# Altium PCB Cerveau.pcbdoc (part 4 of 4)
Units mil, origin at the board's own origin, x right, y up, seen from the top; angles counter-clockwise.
Board outline 3985.6 x 3546.5 mil, 2 copper layers (Top Layer, Bottom Layer), stack 62.2 mil thick; 170 components, 173 nets, 734 pads, 576 vias.
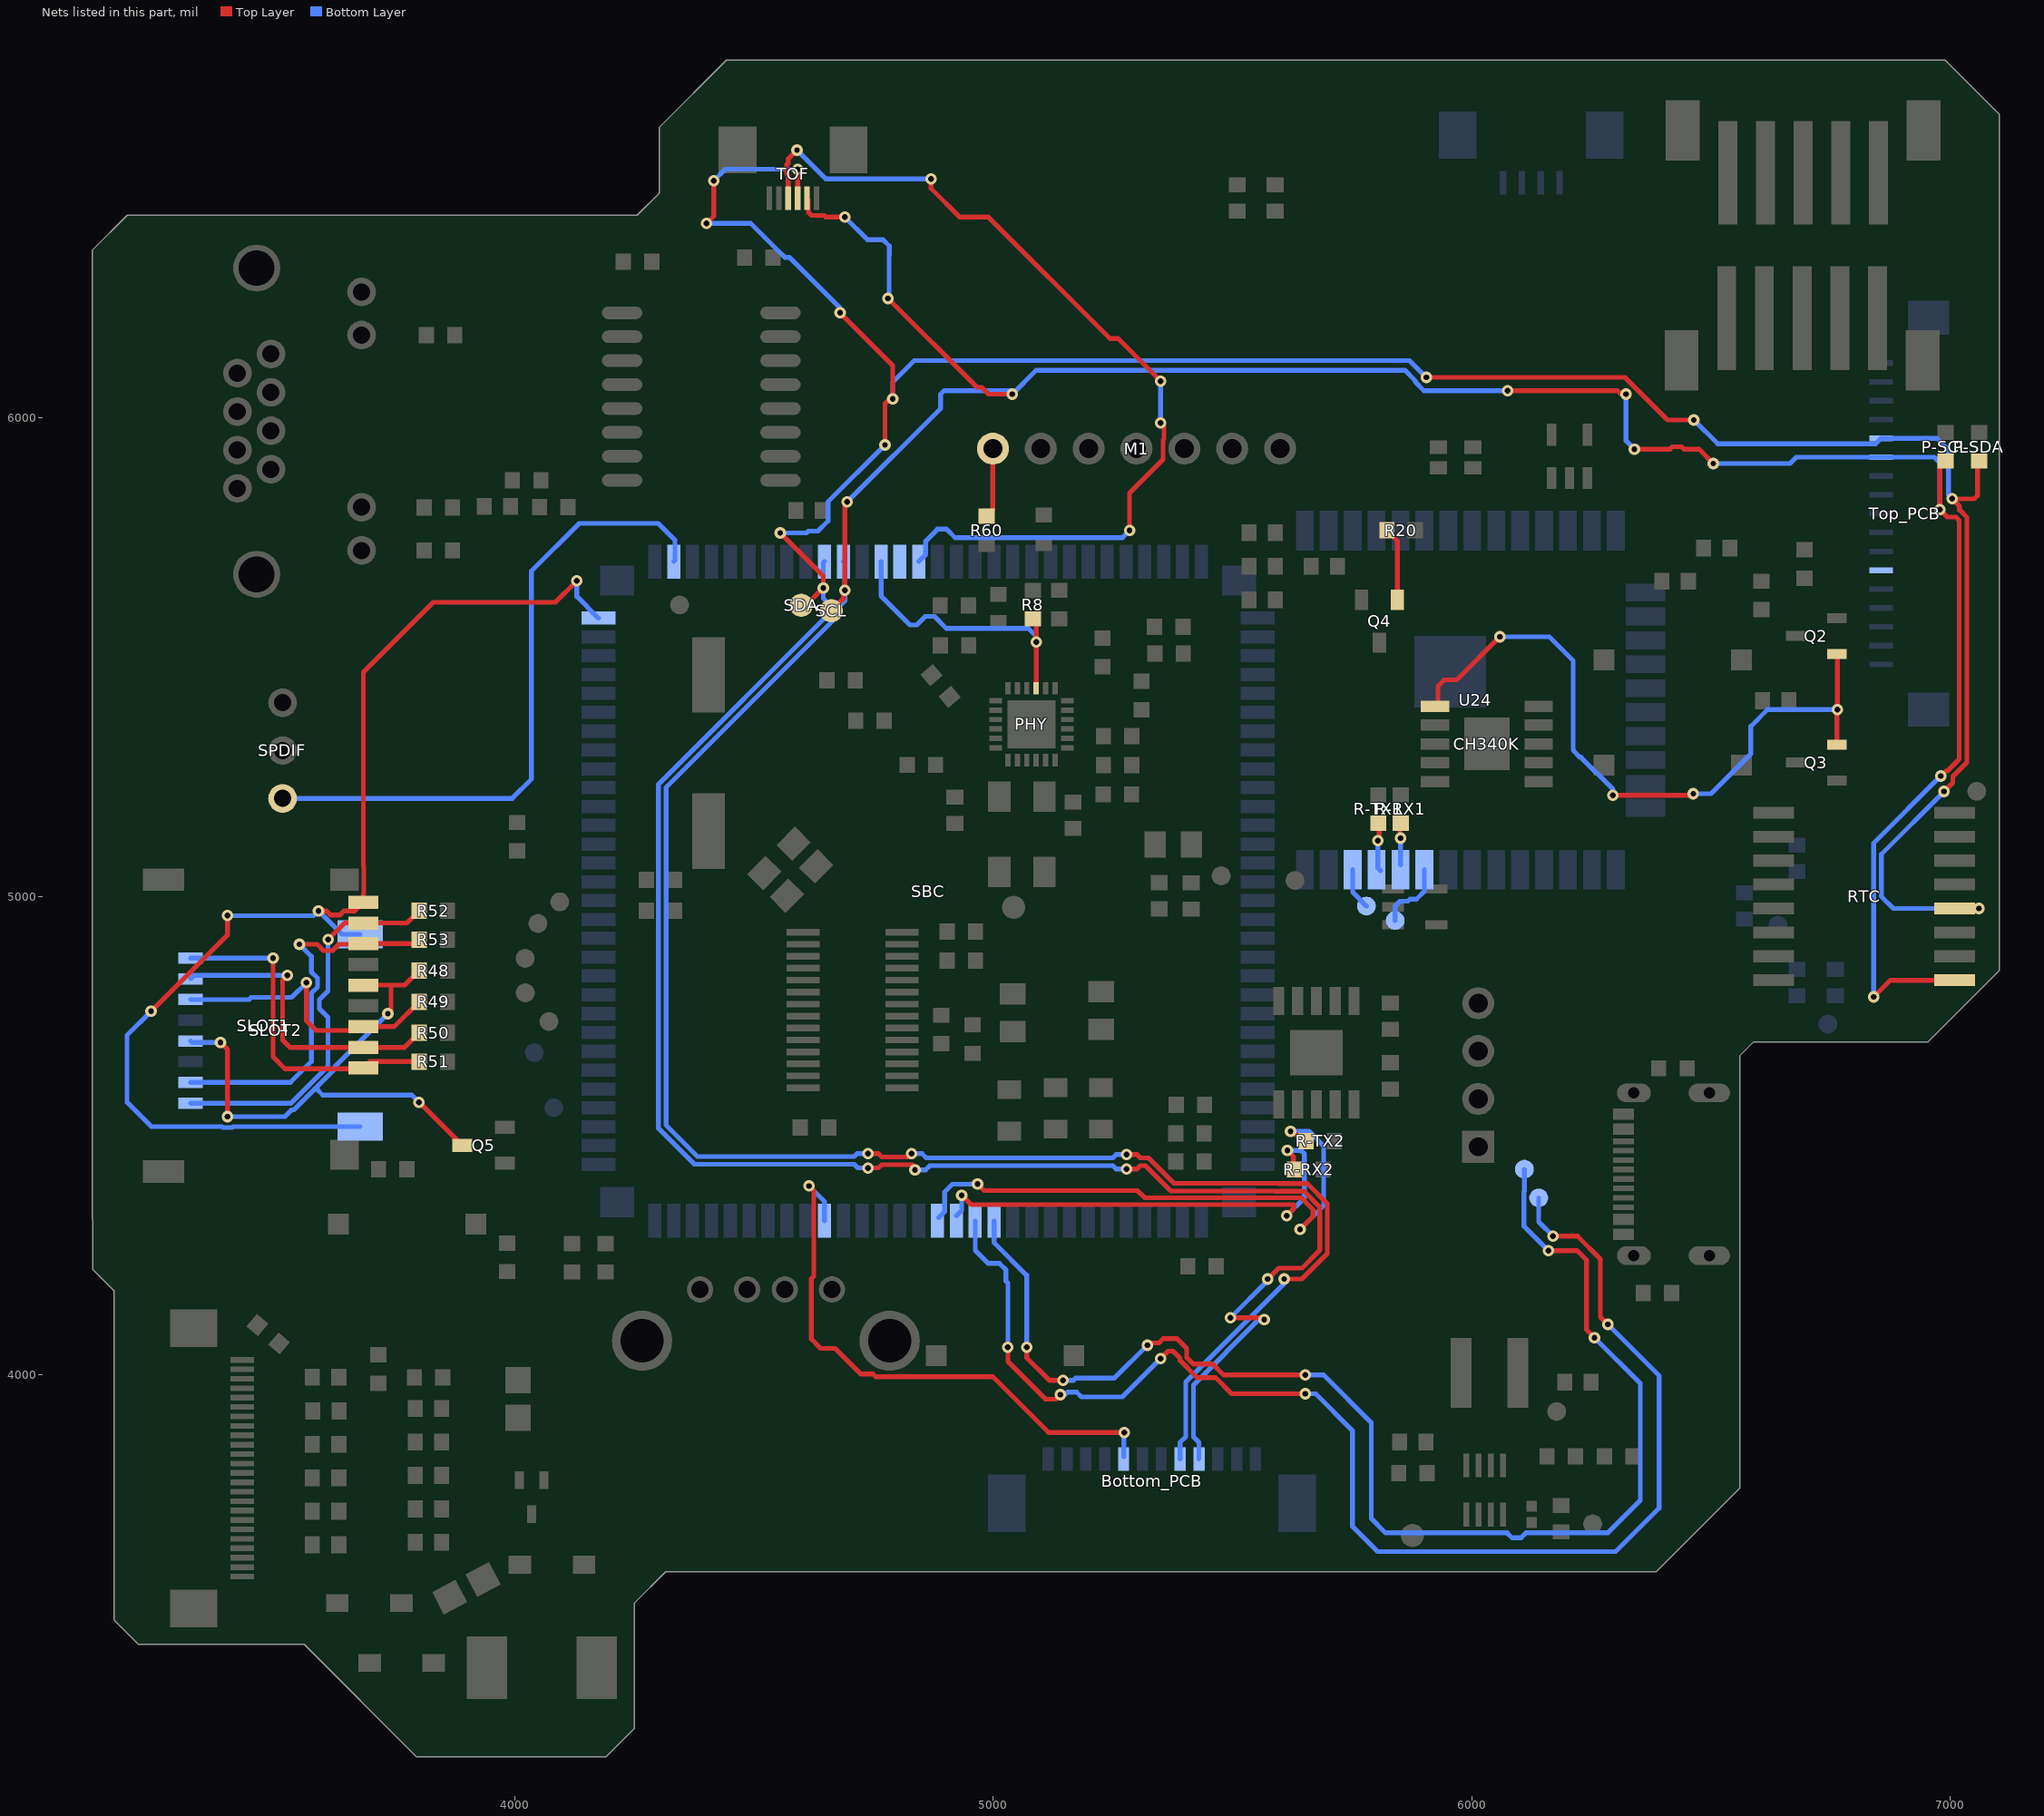
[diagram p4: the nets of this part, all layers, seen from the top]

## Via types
v1: diameter 24, hole 12, Top Layer to Bottom Layer, 576 vias

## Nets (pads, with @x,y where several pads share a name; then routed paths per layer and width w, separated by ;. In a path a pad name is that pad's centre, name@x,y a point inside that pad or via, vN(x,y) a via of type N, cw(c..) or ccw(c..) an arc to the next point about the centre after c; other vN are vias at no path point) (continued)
PHONE_R: Bottom_PCB.8 SBC.81 | length 1198.7
  Top Layer w10: v1(4615,4395) 4625.2,4384.8 4625.2,4206.2 4620,4201.1 4620,4075 4639.6,4055.4 4669.8,4055.4 4723.4,4001.8 4748.8,4001.8 4754.4,3996.2 4999.3,3996.2 5115.8,3879.6 v1(5273.8,3879.6)
  Bottom Layer w10: v1(4615,4395) 4647.4,4362.6 SBC.81@4647.4,4322 ; Bottom_PCB.8@5272.8,3828.9 5272.8,3878.6 v1(5273.8,3879.6)
PHY_RST: PHY.15 R8.1 SBC.13 | length 603.8
  Top Layer w10: R8.1@5082.9,5578.6 5089.8,5571.7 PHY.15@5089.8,5435.1
  Bottom Layer w10: SBC.13@4765.6,5700 4765.6,5628.2 4826.3,5567.5 4840.1,5567.5 4858,5585.4 4877,5585.4 4902.1,5560.3 5073.2,5560.3 5090,5543.4 v1(5090,5532.1)
RST: SBC.14
RST_CMPT: Q4.1 R20.1 | length 154.4
  Top Layer w10: R20.1@5822.6,5765.3 5844.6,5743.2 Q4.1@5844.6,5620
RTS: CH340K.6 Q2.1 Q3.2 | length 1474.4
  Top Layer w10: CH340K.6@5929.3,5393.8 5929.3,5439.5 5941.2,5451.3 ; 5942.1,5452.7 5968.7,5452.7 v1(6058.7,5542.8) ; v1(6295.2,5211.7) 6459.9,5211.7 v1(6463,5214.8) ; Q2.1@6763.3,5506.9 6764.2,5506.1 v1(6764.2,5390.7) 6763.4,5389.9 Q3.2@6763.4,5317.4
  Bottom Layer w10: v1(6058.7,5542.8) 6162.2,5542.8 6211.9,5493.1 6211.9,5307.4 6212.9,5306.4 6212.9,5304.4 6226.4,5290.9 6228.4,5290.9 6295.2,5224.1 v1(6295.2,5211.7) ; v1(6463,5214.8) 6499.9,5214.8 6583.2,5298.1 6583.2,5355.7 6618.1,5390.7 v1(6764.2,5390.7)
RX-1: R-RX1.2 U24.34 | length 84.7
  Top Layer w10: R-RX1.2@5849.7,5150.6 5849.7,5123.4 v1(5851.3,5121.8)
  Bottom Layer w10: U24.34@5851.3,5066.6 v1(5851.3,5121.8)
RX-2: R-RX2.2 SBC.74 | length 1007
  Top Layer w10: v1(4934.2,4375.6) 4953.8,4356 5627.4,4356 5628.6,4354.8 5628.6,4348.3 v1(5613.1,4332.7) ; v1(5614.8,4469.1) 5627.5,4456.4 R-RX2.2@5627.5,4430.1
  Bottom Layer w10: SBC.74@4922.9,4332.5 4934.2,4343.8 v1(4934.2,4375.6) ; v1(5613.1,4332.7) 5650.5,4370.2 5650.5,4462 5643.5,4469.1 v1(5614.8,4469.1)
SCL: Bottom_PCB.5 P-SCL.1 RTC.1 SBC.11 SCL.1 TOF.2 Top_PCB.12 | length 8491.5
  Top Layer w10: TOF.2@4611.1,6459.1 4613.9,6456.3 4613.9,6429.9 4620.3,6423.5 4646.7,6423.5 4650.2,6420 v1(4690,6420) ; SCL.1@4661.6,5597.3 4687.3,5623.1 v1@4687.3,5639.9 ; v1(4690,5640) 4690,5820 v1(4695,5825) ; v1(4738.2,4462.6) 4760.2,4462.6 4767.2,4455.6 4830.5,4455.6 4830.5,4461.3 v1(4829.2,4462.6) ; v1(4780,6250) 4966,6064 4975.8,6064 4989.8,6050 v1(5040,6050) ; v1(5278.9,4460.6) 5300.9,4460.6 5307.9,4453.6 5324.5,4453.6 5377.5,4400.6 5596.2,4400.6 5596.8,4400 5656.3,4400 5698.3,4358 5698.3,4253.5 5645.2,4200.4 v1(5608.2,4200.4) ; v1(6075,6057.1) 6305,6057.1 6312.1,6049.9 v1(6322.6,6049.9) ; v1(6340,5935) 6414.2,5935 6419.2,5940.1 6438.3,5940.1 6443.4,5935 6475,5935 v1(6505,5905) ; v1(6840,4790) 6875,4825 RTC.1@7009,4825 ; v1(6980.1,5251.7) 6990.8,5262.4 6994.1,5262.4 7018.7,5287 7018.7,5785.8 7011.6,5792.9 6993.9,5792.9 v1(6978.3,5808.5) 6978.3,5898.6 P-SCL.1@6990,5910.3
  Bottom Layer w10: SBC.11@4686.8,5700 4690,5696.8 v1(4690,5640) 4690,5618 4675.5,5603.5 4675.5,5586.9 4316.6,5227.9 4316.6,4522 4382,4456.5 4709.2,4456.5 4715.2,4462.6 v1(4738.2,4462.6) ; v1(4690,6420) 4737,6373 4769.5,6373 4783,6359.5 4783,6340.5 4782.5,6340 4782.5,6252.5 v1(4780,6250) ; v1(4695,5825) 4890,6020 4890,6050 4897.1,6057.1 v1@5040,6057.1 ; v1(4829.2,4462.6) 4851.2,4462.6 4860.2,4453.6 5249.9,4453.6 5256.9,4460.6 v1(5278.9,4460.6) ; v1(5040,6050) 5090,6100 5860,6100 5882,6078 5882,6075.5 5900.4,6057.1 v1(6075,6057.1) ; Bottom_PCB.5@5390.6,3824.3 5390.6,3858.9 5402.3,3870.6 5402.3,3985.4 5607,4190.2 v1@5607,4199.8 ; v1(6322.6,6049.9) 6322.6,5952.4 v1(6340,5935) ; v1(6505,5905) 6665,5905 6678.1,5918.1 Top_PCB.12@6855.3,5918.1 6966.3,5918.1 6978.3,5906.2 v1(6978.3,5808.5) ; v1(6840,4790) 6840,5111.6 v1(6980.1,5251.7)
SCL_ESP: pad.1@5780,4980 pad.1@6110,4430 SBC.72 U24.36 | length 2901.6
  Top Layer w10: v1(5070,4058) 5070,4036 5117.1,3988.9 v1(5145.7,3988.9) ; v1(5322.2,4062.2) 5327,4067 5346.5,4067 5355.5,4076 5383.4,4076 5404.1,4055.4 5404.1,4036.3 5417.6,4022.9 5458.3,4022.9 5481.1,4000 v1(5652,4000) ; v1(6160,4260) 6220,4260 6240,4240 6240,4094.3 v1(6256.6,4077.7)
  Bottom Layer w10: SBC.72@5001.8,4322 5001.8,4276.6 5070,4208.4 v1(5070,4058) ; v1(5145.7,3988.9) 5167.7,3988.9 5172.4,3993.6 5253.6,3993.6 v1(5322.2,4062.2) ; v1(5652,4000) 5690.3,4000 5790,3900.3 5790,3700 5820,3670 6073.9,3670 6084.1,3659.7 6103.2,3659.7 6113.4,3670 6284.3,3670 6352.2,3737.8 6352.2,3982.2 v1(6256.6,4077.7) ; U24.36@5751.1,5056 5751.1,5008.9 pad.1@5780,4980 ; pad.1@6110,4430 6110,4383.4 6109.3,4382.7 6109.3,4310.7 v1(6160,4260)
SD_CD: SBC.120 SLOT1.CD SLOT2.9 | length 2500.8
  Top Layer w10: v1(3240,4760) 3400,4920 v1(3400,4960) ; v1(3590,4970) 3606.6,4970 3615.5,4961.1 3634.5,4961.1 3643.4,4970 3665.8,4970 SLOT1.CD@3683.7,4987.9 3683.7,5005.8 3684.8,5006.9 3684.8,5063.3 3683.7,5064.4 3683.7,5468.7 3830,5615 4085,5615 v1(4130,5660)
  Bottom Layer w10: v1(3240,4760) 3190,4710 3190,4570 3240.8,4519.2 3388.3,4519.2 3390.5,4517 3409.5,4517 3411.7,4519.2 SLOT2.9@3677,4519.2 ; v1(3400,4960) 3580,4960 v1(3590,4970) 3639.2,4920.8 SLOT2.9@3677,4920.8 ; v1(4130,5660) 4130,5626.9 SBC.120@4175,5581.9
SD_CLK: Q5.3 R48.2 SLOT1.5 SLOT2.5 | length 1198.6
  Top Layer w10: v1(3385,4695) 3400,4680 v1(3400,4540) ; SLOT1.5@3683.7,4814.6 3741.4,4814.6 ; v1(3735,4755) 3741.4,4761.4 3741.4,4814.6 ; v1(3800,4570) 3800.3,4570 Q5.3@3890.3,4480 ; R48.2@3800.3,4845 3770,4814.6 3741.4,4814.6
  Bottom Layer w10: SLOT2.5@3322.7,4698 3325.7,4695 v1(3385,4695) ; v1(3400,4540) 3520,4540 3534.1,4554.1 3538.9,4554.1 3584.3,4599.5 ; v1(3735,4755) 3624,4644 3624,4639.2 3584.3,4599.5 ; v1(3800,4570) 3785,4585 3598.8,4585 3584.3,4599.5
SD_CMD: R49.2 SLOT1.3 SLOT2.3 | length 605.4
  Top Layer w10: v1(3565,4820) 3565,4740 3585,4720 3675.6,4720 SLOT1.3@3683.7,4728 3748.4,4728 R49.2@3800.3,4780
  Bottom Layer w10: SLOT2.3@3322.7,4784.6 3444.8,4784.6 3449.2,4789 3534,4789 v1(3565,4820)
SD_DAT0: R53.2 SLOT1.7 SLOT2.7 | length 801.7
  Top Layer w10: v1(3550,4900) 3587.5,4900 3600.5,4887 3619.5,4887 3632.5,4900 3682.4,4900 SLOT1.7@3683.7,4901.3 3791.6,4901.3 R53.2@3800.3,4910
  Bottom Layer w10: SLOT2.7@3322.7,4611.4 3531.4,4611.4 3575,4655 3575,4797.5 3588,4810.5 3588,4829.5 3575,4842.5 3575,4875 v1(3550,4900)
SD_DAT1: R52.2 SLOT1.8 SLOT2.8 | length 814.2
  Top Layer w10: v1(3610,4910) 3644.6,4944.6 SLOT1.8@3683.7,4944.6 3774.9,4944.6 R52.2@3800.3,4970
  Bottom Layer w10: SLOT2.8@3322.7,4568.1 3533.1,4568.1 3610,4645 3610,4747.5 3592,4765.5 3592,4784.5 3610,4802.5 v1(3610,4910)
SD_DAT2: R51.2 SLOT1.1 SLOT2.1 | length 700.4
  Top Layer w10: v1(3495,4871.2) 3495,4665 3520,4640 3682.3,4640 SLOT1.1@3683.7,4641.4 3697.3,4655 R51.2@3800.3,4655
  Bottom Layer w10: SLOT2.1@3322.7,4871.2 v1(3495,4871.2)
SD_DAT3: R50.2 SLOT1.2 SLOT2.2 | length 648.6
  Top Layer w10: v1(3525,4835) 3515,4825 3515,4700 3530.3,4684.7 SLOT1.2@3683.7,4684.7 3770.1,4684.7 R50.2@3800.3,4715
  Bottom Layer w10: SLOT2.2@3322.7,4827.9 3329.8,4835 v1(3525,4835)
SDA: Bottom_PCB.4 P-SDA.1 RTC.4 SBC.10 SDA.1 TOF.3 Top_PCB.13 | length 8917.7
  Top Layer w10: v1(4401.1,6407) 4416.1,6422 v1(4416.1,6496.1) ; v1(4555,5760) 4645,5670 v1(4645,5645) 4606.5,5606.5 SDA.1@4600.4,5606.5 ; TOF.3@4591.4,6459.1 v1(4591.4,6520) ; v1(4680,6220) 4790,6110 v1(4790,6040) 4783.8,6040 4773.8,6030 v1(4773.8,5943.8) ; v1(4738.2,4432.6) 4760.2,4432.6 4767.2,4439.6 4830.5,4439.6 4836.5,4433.5 v1(4836.5,4428.6) ; v1(5278.9,4430.6) 5300.9,4430.6 5307.9,4437.6 5317.9,4437.6 5370.9,4384.6 5589.6,4384.6 5590.2,4384 5649.7,4384 5682.3,4351.4 5682.3,4260.2 5645.6,4223.4 5596.7,4223.4 v1(5573.7,4200.4) ; v1(5495.8,4119.5) 5562.7,4119.5 v1(5566.4,4115.8) ; v1(5905,6085) 6320,6085 6409,5996 v1(6464,5996) ; v1(6987.2,5219.5) 7005.4,5237.7 7005.4,5251.1 7034.7,5280.3 7034.7,5792.5 7019.3,5807.9 7019.3,5815.7 v1(7003.7,5831.2) 7050,5831.2 7057.1,5838.3 7057.1,5907.4 P-SDA.1@7060,5910.3 ; RTC.4@7009,4975 v1(7060,4975)
  Bottom Layer w10: v1(4401.1,6407) 4493.2,6407 4550.2,6350 4564.2,6336 4574,6336 4680,6230 v1(4680,6220) ; v1(4416.1,6496.1) 4440,6520 v1(4591.4,6520) ; v1(4555,5760) 4609.9,5760 4613.8,5763.9 4633.9,5763.9 4655,5785 4655,5825 v1(4773.8,5943.8) ; SBC.10@4647.4,5700 4645,5697.6 v1(4645,5645) 4645,5623 4659.5,5608.5 4659.5,5593.5 4300.6,5234.6 4300.6,4515.3 4375.4,4440.5 4709.2,4440.5 4717.2,4432.6 v1(4738.2,4432.6) ; v1(4790,6040) 4790,6075 4835,6120 5870,6120 v1(5905,6085) ; v1(4836.5,4428.6) 4858.5,4428.6 4867.5,4437.6 5249.9,4437.6 5256.9,4430.6 v1(5278.9,4430.6) ; Bottom_PCB.4@5430,3824.3 5430,3858.9 5418.3,3870.6 5418.3,3978.8 5555.2,4115.8 v1(5566.4,4115.8) ; v1(5495.8,4119.5) 5573.7,4197.4 v1(5573.7,4200.4) ; v1(6464,5996) 6514,5946.1 6843.9,5946.1 Top_PCB.13@6855.3,5957.5 6972.1,5957.5 6996.3,5933.3 6996.3,5838.7 v1(7003.7,5831.2) ; v1(6987.2,5219.5) 6856,5088.2 6856,5000 6881,4975 v1(7060,4975)
SDA_ESP: pad.1@5840,4950 pad.1@6140,4370 SBC.73 U24.33 | length 3042
  Top Layer w10: v1(5030.6,4058) 5030.6,4028.1 5109.2,3949.5 5131.1,3949.5 v1(5140.5,3958.9) ; v1(5350,4034.3) 5365.6,4049.9 5375.6,4049.9 5390.1,4035.4 5390.1,4030.5 5426.3,3994.3 5464.7,3994.3 5498.4,3960.6 v1(5652,3960.6) ; v1(6170,4290) 6221,4290 6268.9,4242.1 6268.9,4121.1 v1(6284.4,4105.6)
  Bottom Layer w10: SBC.73@4962.4,4322 4962.4,4260.3 4989.7,4233 5013.2,4233 5026.7,4219.5 5026.7,4196 5030.6,4192.1 v1(5030.6,4058) ; v1(5140.5,3958.9) 5150.4,3958.9 5155.5,3964 5174.5,3964 5184.3,3954.2 5269.9,3954.2 v1(5350,4034.3) ; v1(5652,3960.6) 5674,3960.6 5750.6,3884 5750.6,3683.7 5803.7,3630.6 6300.6,3630.6 6391.5,3721.5 6391.5,3998.5 v1(6284.4,4105.6) ; pad.1@5840,4950 5840,4980 5850,4990 5866.2,4990 5870.7,4994.5 5884.5,4994.5 5901.1,5011.1 U24.33@5901.1,5056 ; pad.1@6140,4370 6140,4320 v1(6170,4290)
SPDIF: SBC.2 SPDIF.1 | length 1373.5
  Bottom Layer w10: SPDIF.1@3515,5205 3995,5205 4035,5245 4035,5680 4135,5780 4300,5780 4335,5745 4335,5702.5 SBC.2@4332.5,5700
TX-1: R-TX1.2 U24.35 | length 101.7
  Top Layer w10: v1(5804.1,5117) 5806.5,5119.4 R-TX1.2@5806.5,5152.2
  Bottom Layer w10: v1(5804.1,5117) 5804.1,5059.4 U24.35@5809.7,5053.8
TX-2: R-TX2.2 SBC.75 | length 1224.4
  Top Layer w10: v1(4967.2,4399.2) 4981,4385.4 5301.3,4385.4 5316.8,4370 5643.9,4370 5668.3,4345.6 5668.3,4331.2 v1(5641.4,4304.4) ; v1(5621.5,4509.2) 5626.4,4509.2 R-TX2.2@5650.1,4485.5
  Bottom Layer w10: SBC.75@4886.4,4329.2 4898.3,4341.1 4898.3,4382.1 4914.7,4398.6 4955.7,4398.6 4956.4,4399.2 v1(4967.2,4399.2) ; v1(5621.5,4509.2) 5660.1,4509.2 5690.7,4478.6 5690.7,4353.6 v1(5641.4,4304.4)
WS: Top_PCB.6
WS/LRCLK: M1.1 R60.2 | length 144.3
  Top Layer w10: R60.2@4986.6,5795 4998.8,5807.2 M1.1@4998.8,5934.2
XSHUT: SBC.15 TOF.4 | length 1926.9
  Top Layer w10: TOF.4@4571.7,6459.1 4571.7,6507.2 4568.4,6510.5 4568.4,6529.5 4571.7,6532.8 4571.7,6541.7 v1(4590,6560) ; v1(4870,6500) 4870,6480 4930,6420 4990,6420 5244,6166 5261,6166 v1(5350,6077) ; v1(5285,5765) 5285,5843.5 5355,5913.5 5355,5954.4 5357.1,5956.4 5357.1,5982.9 v1(5350,5990)
  Bottom Layer w10: v1(4590,6560) 4650,6500 v1(4870,6500) ; SBC.15@4844.3,5700 4858.9,5714.6 4858.9,5743 4883.6,5767.8 4902.7,5767.8 4920.4,5750 5270,5750 v1(5285,5765) ; v1(5350,5990) v1(5350,6077)
pads on no net: Buck_1.1 CH340K-2.4 CH340K-2.5 CH340K-2.6 CH340K.5 E-INK.1 E-INK.6 E-INK.7 FILT.12 FILT.13 LED16.1 M1.4 PHY.2 RJ45.4 RJ45.5 RJ45.7 RJ45.8 RTC.3 RTC.6 RTC.7 RTC.9 RTC.10 RTC.11 RTC.12 RTC.13 SBC.17 SBC.18 SBC.19 SBC.20 SBC.21 SBC.22 SBC.23 SBC.24 SBC.25 SBC.26 SBC.27 SBC.28 SBC.39 SBC.46 SBC.47 SBC.48 SBC.49 SBC.50 SBC.51 SBC.52 SBC.53 SBC.54 SBC.55 SBC.56 SBC.57 SBC.62 SBC.63 SBC.64 SBC.67 SBC.69 SBC.71 SBC.76 SBC.77 SBC.78 SBC.79 SBC.83 SBC.84 SBC.85 SBC.86 SBC.87 SBC.88 SBC.89 SBC.90 SBC.91 SBC.92 SBC.95 SBC.104 U24.4 U24.5 U24.6 U24.8 U24.9 U24.12 U24.13 U24.14 U24.16 U24.17 U24.18 U24.19 U24.20 U24.21 U24.22 U24.23 U24.24 U24.26 U24.27 U24.29 U24.32 USB-C2.A8 USB-C2.B8 USB_SWITCH.4 USB_SWITCH.5 USB_SWITCH.12 USB_SWITCH.13 USB_SWITCH.21 USB_SWITCH.27 USB_SWITCH.28 X3.2 X3.4

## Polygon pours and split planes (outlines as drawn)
GND on Top Layer (solid, remove dead copper, pour order 2): 3000,6850 3000,3000 7220,3000 7220,6850
5V on Top Layer (solid, remove dead copper, pour order 0): 6723,5806.7 6724.9,6630 6723.2,6630.3 6723.3,6653.5 6896.7,6653.9 6895.4,6499.1 6935.2,6454.5 6935.2,6211.7 6931.8,6208.3 6909.9,6208.3 6896.6,6195.1 6896.6,5996.9 6956.9,5936.6 6964.7,4847.6 6830,4710 6160.7,4710 6160.7,4854.7 6218.2,4910.8 6778.2,4910.9 6820.3,4972.7 6820.3,5719.6
GND on Bottom Layer (solid, remove dead copper, pour order 10): 3010,6850 3010,3110 7200,3110 7200,6850
5V on Bottom Layer (solid, remove dead copper, pour order 8): 6171.6,4860.3 6217.3,4906 6500.8,4906 6502.7,4904.1 6502.7,4806.1 6479.9,4783.2 6288.7,4783.2 6255.4,4749.9 6255.4,4311.4 6174.5,4311 6174.5,4602.4 6171.6,4605.3

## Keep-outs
Board Outline Layer:
  region: 4411.3,6558.4 4410.9,6552.9 4409.7,6547.5 4407.8,6542.4 4405.3,6537.5 4402,6533.1 4398.2,6529.1 4393.9,6525.8 4389.1,6523 4384,6520.9 4378.7,6519.6 4373.3,6519 4367.8,6519.2 4362.4,6520.2 4357.1,6521.9 4352.2,6524.3 4347.6,6527.4 4343.6,6531 4340,6535.3 4337.1,6539.9 4334.9,6544.9 4333.4,6550.2 4332.6,6555.6 4332.6,6561.1 4333.4,6566.6 4334.9,6571.9 4337.1,6576.9 4340,6581.5 4343.6,6585.7 4347.6,6589.4 4352.2,6592.5 4357.1,6594.9 4362.4,6596.6 4367.8,6597.5 4373.3,6597.7 4378.7,6597.2 4384,6595.8 4389.1,6593.8 4393.9,6591 4398.2,6587.6 4402,6583.7 4405.3,6579.3 4407.8,6574.4 4409.7,6569.2 4410.9,6563.9
  region: 4411.3,6558.4 4410.9,6552.9 4409.7,6547.5 4407.8,6542.4 4405.3,6537.5 4402,6533.1 4398.2,6529.1 4393.9,6525.8 4389.1,6523 4384,6520.9 4378.7,6519.6 4373.3,6519 4367.8,6519.2 4362.4,6520.2 4357.1,6521.9 4352.2,6524.3 4347.6,6527.4 4343.6,6531 4340,6535.3 4337.1,6539.9 4334.9,6544.9 4333.4,6550.2 4332.6,6555.6 4332.6,6561.1 4333.4,6566.6 4334.9,6571.9 4337.1,6576.9 4340,6581.5 4343.6,6585.7 4347.6,6589.4 4352.2,6592.5 4357.1,6594.9 4362.4,6596.6 4367.8,6597.5 4373.3,6597.7 4378.7,6597.2 4384,6595.8 4389.1,6593.8 4393.9,6591 4398.2,6587.6 4402,6583.7 4405.3,6579.3 4407.8,6574.4 4409.7,6569.2 4410.9,6563.9
  region: 3235.1,4311.8 3234.7,4306.3 3233.6,4301 3231.7,4295.8 3229.1,4290.9 3225.9,4286.5 3222.1,4282.6 3217.8,4279.2 3213,4276.4 3207.9,4274.4 3202.6,4273 3197.1,4272.5 3191.6,4272.7 3186.2,4273.6 3181,4275.3 3176.1,4277.7 3171.5,4280.8 3167.4,4284.5 3163.9,4288.7 3161,4293.3 3158.8,4298.3 3157.2,4303.6 3156.5,4309.1 3156.5,4314.6 3157.2,4320 3158.8,4325.3 3161,4330.3 3163.9,4335 3167.4,4339.2 3171.5,4342.8 3176.1,4345.9 3181,4348.3 3186.2,4350 3191.6,4351 3197.1,4351.2 3202.6,4350.6 3207.9,4349.3 3213,4347.2 3217.8,4344.4 3222.1,4341.1 3225.9,4337.1 3229.1,4332.7 3231.7,4327.8 3233.6,4322.7 3234.7,4317.3
  region: 3235.1,4311.8 3234.7,4306.3 3233.6,4301 3231.7,4295.8 3229.1,4290.9 3225.9,4286.5 3222.1,4282.6 3217.8,4279.2 3213,4276.4 3207.9,4274.4 3202.6,4273 3197.1,4272.5 3191.6,4272.7 3186.2,4273.6 3181,4275.3 3176.1,4277.7 3171.5,4280.8 3167.4,4284.5 3163.9,4288.7 3161,4293.3 3158.8,4298.3 3157.2,4303.6 3156.5,4309.1 3156.5,4314.6 3157.2,4320 3158.8,4325.3 3161,4330.3 3163.9,4335 3167.4,4339.2 3171.5,4342.8 3176.1,4345.9 3181,4348.3 3186.2,4350 3191.6,4351 3197.1,4351.2 3202.6,4350.6 3207.9,4349.3 3213,4347.2 3217.8,4344.4 3222.1,4341.1 3225.9,4337.1 3229.1,4332.7 3231.7,4327.8 3233.6,4322.7 3234.7,4317.3
  region: 4949,3809.6 4948.6,3804.1 4947.4,3798.7 4945.6,3793.6 4943,3788.7 4939.7,3784.3 4935.9,3780.3 4931.6,3776.9 4926.8,3774.2 4921.8,3772.1 4916.4,3770.8 4911,3770.2 4905.5,3770.4 4900.1,3771.4 4894.8,3773.1 4889.9,3775.5 4885.3,3778.6 4881.3,3782.2 4877.7,3786.4 4874.8,3791.1 4872.6,3796.1 4871.1,3801.4 4870.3,3806.8 4870.3,3812.3 4871.1,3817.8 4872.6,3823 4874.8,3828.1 4877.7,3832.7 4881.3,3836.9 4885.3,3840.6 4889.9,3843.7 4894.8,3846.1 4900.1,3847.8 4905.5,3848.7 4911,3848.9 4916.4,3848.3 4921.8,3847 4926.8,3845 4931.6,3842.2 4935.9,3838.8 4939.7,3834.9 4943,3830.4 4945.6,3825.6 4947.4,3820.4 4948.6,3815.1
  region: 4949,3809.6 4948.6,3804.1 4947.4,3798.7 4945.6,3793.6 4943,3788.7 4939.7,3784.3 4935.9,3780.3 4931.6,3776.9 4926.8,3774.2 4921.8,3772.1 4916.4,3770.8 4911,3770.2 4905.5,3770.4 4900.1,3771.4 4894.8,3773.1 4889.9,3775.5 4885.3,3778.6 4881.3,3782.2 4877.7,3786.4 4874.8,3791.1 4872.6,3796.1 4871.1,3801.4 4870.3,3806.8 4870.3,3812.3 4871.1,3817.8 4872.6,3823 4874.8,3828.1 4877.7,3832.7 4881.3,3836.9 4885.3,3840.6 4889.9,3843.7 4894.8,3846.1 4900.1,3847.8 4905.5,3848.7 4911,3848.9 4916.4,3848.3 4921.8,3847 4926.8,3845 4931.6,3842.2 4935.9,3838.8 4939.7,3834.9 4943,3830.4 4945.6,3825.6 4947.4,3820.4 4948.6,3815.1
  region: 6486.3,4030.8 6485.9,4025.3 6484.8,4019.9 6482.9,4014.8 6480.3,4009.9 6477.1,4005.5 6473.3,4001.5 6468.9,3998.1 6464.2,3995.4 6459.1,3993.3 6453.8,3992 6448.3,3991.4 6442.8,3991.6 6437.4,3992.6 6432.2,3994.3 6427.2,3996.7 6422.7,3999.8 6418.6,4003.4 6415.1,4007.6 6412.2,4012.3 6409.9,4017.3 6408.4,4022.6 6407.6,4028 6407.6,4033.5 6408.4,4039 6409.9,4044.3 6412.2,4049.3 6415.1,4053.9 6418.6,4058.1 6422.7,4061.8 6427.2,4064.9 6432.2,4067.3 6437.4,4069 6442.8,4069.9 6448.3,4070.1 6453.8,4069.6 6459.1,4068.2 6464.2,4066.2 6468.9,4063.4 6473.3,4060 6477.1,4056.1 6480.3,4051.6 6482.9,4046.8 6484.8,4041.6 6485.9,4036.3
  region: 6486.3,4030.8 6485.9,4025.3 6484.8,4019.9 6482.9,4014.8 6480.3,4009.9 6477.1,4005.5 6473.3,4001.5 6468.9,3998.1 6464.2,3995.4 6459.1,3993.3 6453.8,3992 6448.3,3991.4 6442.8,3991.6 6437.4,3992.6 6432.2,3994.3 6427.2,3996.7 6422.7,3999.8 6418.6,4003.4 6415.1,4007.6 6412.2,4012.3 6409.9,4017.3 6408.4,4022.6 6407.6,4028 6407.6,4033.5 6408.4,4039 6409.9,4044.3 6412.2,4049.3 6415.1,4053.9 6418.6,4058.1 6422.7,4061.8 6427.2,4064.9 6432.2,4067.3 6437.4,4069 6442.8,4069.9 6448.3,4070.1 6453.8,4069.6 6459.1,4068.2 6464.2,4066.2 6468.9,4063.4 6473.3,4060 6477.1,4056.1 6480.3,4051.6 6482.9,4046.8 6484.8,4041.6 6485.9,4036.3
  region: 7054.9,6394.5 7054.5,6389 7053.3,6383.6 7051.5,6378.5 7048.9,6373.6 7045.7,6369.2 7041.8,6365.2 7037.5,6361.9 7032.8,6359.1 7027.7,6357.1 7022.3,6355.7 7016.9,6355.2 7011.4,6355.3 7006,6356.3 7000.7,6358 6995.8,6360.4 6991.3,6363.5 6987.2,6367.1 6983.6,6371.4 6980.7,6376 6978.5,6381 6977,6386.3 6976.2,6391.8 6976.2,6397.2 6977,6402.7 6978.5,6408 6980.7,6413 6983.6,6417.6 6987.2,6421.8 6991.3,6425.5 6995.8,6428.6 7000.7,6431 7006,6432.7 7011.4,6433.7 7016.9,6433.8 7022.3,6433.3 7027.7,6431.9 7032.8,6429.9 7037.5,6427.1 7041.8,6423.8 7045.7,6419.8 7048.9,6415.4 7051.5,6410.5 7053.3,6405.3 7054.5,6400
  region: 7054.9,6394.5 7054.5,6389 7053.3,6383.6 7051.5,6378.5 7048.9,6373.6 7045.7,6369.2 7041.8,6365.2 7037.5,6361.9 7032.8,6359.1 7027.7,6357.1 7022.3,6355.7 7016.9,6355.2 7011.4,6355.3 7006,6356.3 7000.7,6358 6995.8,6360.4 6991.3,6363.5 6987.2,6367.1 6983.6,6371.4 6980.7,6376 6978.5,6381 6977,6386.3 6976.2,6391.8 6976.2,6397.2 6977,6402.7 6978.5,6408 6980.7,6413 6983.6,6417.6 6987.2,6421.8 6991.3,6425.5 6995.8,6428.6 7000.7,6431 7006,6432.7 7011.4,6433.7 7016.9,6433.8 7022.3,6433.3 7027.7,6431.9 7032.8,6429.9 7037.5,6427.1 7041.8,6423.8 7045.7,6419.8 7048.9,6415.4 7051.5,6410.5 7053.3,6405.3 7054.5,6400
  region: 5872.9,6662.5 5872.6,6657 5871.4,6651.6 5869.5,6646.5 5867,6641.6 5863.7,6637.2 5859.9,6633.2 5855.6,6629.9 5850.8,6627.1 5845.7,6625 5840.4,6623.7 5834.9,6623.1 5829.5,6623.3 5824,6624.3 5818.8,6626 5813.9,6628.4 5809.3,6631.5 5805.2,6635.1 5801.7,6639.3 5798.8,6644 5796.6,6649 5795.1,6654.3 5794.3,6659.7 5794.3,6665.2 5795.1,6670.7 5796.6,6676 5798.8,6681 5801.7,6685.6 5805.2,6689.8 5809.3,6693.5 5813.9,6696.6 5818.8,6699 5824,6700.7 5829.5,6701.6 5834.9,6701.8 5840.4,6701.3 5845.7,6699.9 5850.8,6697.9 5855.6,6695.1 5859.9,6691.7 5863.7,6687.8 5867,6683.4 5869.5,6678.5 5871.4,6673.3 5872.6,6668
  region: 5872.9,6662.5 5872.6,6657 5871.4,6651.6 5869.5,6646.5 5867,6641.6 5863.7,6637.2 5859.9,6633.2 5855.6,6629.9 5850.8,6627.1 5845.7,6625 5840.4,6623.7 5834.9,6623.1 5829.5,6623.3 5824,6624.3 5818.8,6626 5813.9,6628.4 5809.3,6631.5 5805.2,6635.1 5801.7,6639.3 5798.8,6644 5796.6,6649 5795.1,6654.3 5794.3,6659.7 5794.3,6665.2 5795.1,6670.7 5796.6,6676 5798.8,6681 5801.7,6685.6 5805.2,6689.8 5809.3,6693.5 5813.9,6696.6 5818.8,6699 5824,6700.7 5829.5,6701.6 5834.9,6701.8 5840.4,6701.3 5845.7,6699.9 5850.8,6697.9 5855.6,6695.1 5859.9,6691.7 5863.7,6687.8 5867,6683.4 5869.5,6678.5 5871.4,6673.3 5872.6,6668
  region: 3268.5,5601.7 3268.1,5596.3 3267,5590.9 3265.1,5585.7 3262.5,5580.9 3259.3,5576.4 3255.5,5572.5 3251.2,5569.1 3246.4,5566.4 3241.3,5564.3 3236,5563 3230.5,5562.4 3225,5562.6 3219.6,5563.5 3214.4,5565.2 3209.5,5567.7 3204.9,5570.7 3200.8,5574.4 3197.3,5578.6 3194.4,5583.3 3192.1,5588.3 3190.6,5593.6 3189.9,5599 3189.9,5604.5 3190.6,5609.9 3192.1,5615.2 3194.4,5620.2 3197.3,5624.9 3200.8,5629.1 3204.9,5632.8 3209.5,5635.8 3214.4,5638.3 3219.6,5640 3225,5640.9 3230.5,5641.1 3236,5640.5 3241.3,5639.2 3246.4,5637.1 3251.2,5634.4 3255.5,5631 3259.3,5627.1 3262.5,5622.6 3265.1,5617.8 3267,5612.6 3268.1,5607.2
  region: 3268.5,5601.7 3268.1,5596.3 3267,5590.9 3265.1,5585.7 3262.5,5580.9 3259.3,5576.4 3255.5,5572.5 3251.2,5569.1 3246.4,5566.4 3241.3,5564.3 3236,5563 3230.5,5562.4 3225,5562.6 3219.6,5563.5 3214.4,5565.2 3209.5,5567.7 3204.9,5570.7 3200.8,5574.4 3197.3,5578.6 3194.4,5583.3 3192.1,5588.3 3190.6,5593.6 3189.9,5599 3189.9,5604.5 3190.6,5609.9 3192.1,5615.2 3194.4,5620.2 3197.3,5624.9 3200.8,5629.1 3204.9,5632.8 3209.5,5635.8 3214.4,5638.3 3219.6,5640 3225,5640.9 3230.5,5641.1 3236,5640.5 3241.3,5639.2 3246.4,5637.1 3251.2,5634.4 3255.5,5631 3259.3,5627.1 3262.5,5622.6 3265.1,5617.8 3267,5612.6 3268.1,5607.2
  lines w0.1: 3156.5,4309.1 3157.2,4303.6 3158.8,4298.3 3161,4293.3 3163.9,4288.7 3167.4,4284.5 3171.5,4280.8 3176.1,4277.7 3181,4275.3 3186.2,4273.6 3191.6,4272.7 3197.1,4272.5 3202.6,4273 3207.9,4274.4 3213,4276.4 3217.8,4279.2 3222.1,4282.6 3225.9,4286.5 3229.1,4290.9 3231.7,4295.8 3233.6,4301 3234.7,4306.3 3235.1,4311.8 3234.7,4317.3 3233.6,4322.7 3231.7,4327.8 3229.1,4332.7 3225.9,4337.1 3222.1,4341.1 3217.8,4344.4 3213,4347.2 3207.9,4349.3 3202.6,4350.6 3197.1,4351.2 3191.6,4351 3186.2,4350 3181,4348.3 3176.1,4345.9 3171.5,4342.8 3167.4,4339.2 3163.9,4335 3161,4330.3 3158.8,4325.3 3157.2,4320 3156.5,4314.6 3156.5,4309.1 ; 3189.9,5599 3190.6,5593.6 3192.1,5588.3 3194.4,5583.3 3197.3,5578.6 3200.8,5574.4 3204.9,5570.7 3209.5,5567.7 3214.4,5565.2 3219.6,5563.5 3225,5562.6 3230.5,5562.4 3236,5563 3241.3,5564.3 3246.4,5566.4 3251.2,5569.1 3255.5,5572.5 3259.3,5576.4 3262.5,5580.9 3265.1,5585.7 3267,5590.9 3268.1,5596.3 3268.5,5601.7 3268.1,5607.2 3267,5612.6 3265.1,5617.8 3262.5,5622.6 3259.3,5627.1 3255.5,5631 3251.2,5634.4 3246.4,5637.1 3241.3,5639.2 3236,5640.5 3230.5,5641.1 3225,5640.9 3219.6,5640 3214.4,5638.3 3209.5,5635.8 3204.9,5632.8 3200.8,5629.1 3197.3,5624.9 3194.4,5620.2 3192.1,5615.2 3190.6,5609.9 3189.9,5604.5 3189.9,5599 ; 4332.6,6555.6 4333.4,6550.2 4334.9,6544.9 4337.1,6539.9 4340,6535.3 4343.6,6531 4347.6,6527.4 4352.2,6524.3 4357.1,6521.9 4362.4,6520.2 4367.8,6519.2 4373.3,6519 4378.7,6519.6 4384,6520.9 4389.1,6523 4393.9,6525.8 4398.2,6529.1 4402,6533.1 4405.3,6537.5 4407.8,6542.4 4409.7,6547.5 4410.9,6552.9 4411.3,6558.4 4410.9,6563.9 4409.7,6569.2 4407.8,6574.4 4405.3,6579.3 4402,6583.7 4398.2,6587.6 4393.9,6591 4389.1,6593.8 4384,6595.8 4378.7,6597.2 4373.3,6597.7 4367.8,6597.5 4362.4,6596.6 4357.1,6594.9 4352.2,6592.5 4347.6,6589.4 4343.6,6585.7 4340,6581.5 4337.1,6576.9 4334.9,6571.9 4333.4,6566.6 4332.6,6561.1 4332.6,6555.6 ; 4870.3,3806.8 4871.1,3801.4 4872.6,3796.1 4874.8,3791.1 4877.7,3786.4 4881.3,3782.2 4885.3,3778.6 4889.9,3775.5 4894.8,3773.1 4900.1,3771.4 4905.5,3770.4 4911,3770.2 4916.4,3770.8 4921.8,3772.1 4926.8,3774.2 4931.6,3776.9 4935.9,3780.3 4939.7,3784.3 4943,3788.7 4945.6,3793.6 4947.4,3798.7 4948.6,3804.1 4949,3809.6 4948.6,3815.1 4947.4,3820.4 4945.6,3825.6 4943,3830.4 4939.7,3834.9 4935.9,3838.8 4931.6,3842.2 4926.8,3845 4921.8,3847 4916.4,3848.3 4911,3848.9 4905.5,3848.7 4900.1,3847.8 4894.8,3846.1 4889.9,3843.7 4885.3,3840.6 4881.3,3836.9 4877.7,3832.7 4874.8,3828.1 4872.6,3823 4871.1,3817.8 4870.3,3812.3 4870.3,3806.8 ; 5794.3,6659.7 5795.1,6654.3 5796.6,6649 5798.8,6644 5801.7,6639.3 5805.2,6635.1 5809.3,6631.5 5813.9,6628.4 5818.8,6626 5824,6624.3 5829.5,6623.3 5834.9,6623.1 5840.4,6623.7 5845.7,6625 5850.8,6627.1 5855.6,6629.9 5859.9,6633.2 5863.7,6637.2 5867,6641.6 5869.5,6646.5 5871.4,6651.6 5872.6,6657 5872.9,6662.5 5872.6,6668 5871.4,6673.3 5869.5,6678.5 5867,6683.4 5863.7,6687.8 5859.9,6691.7 5855.6,6695.1 5850.8,6697.9 5845.7,6699.9 5840.4,6701.3 5834.9,6701.8 5829.5,6701.6 5824,6700.7 5818.8,6699 5813.9,6696.6 5809.3,6693.5 5805.2,6689.8 5801.7,6685.6 5798.8,6681 5796.6,6676 5795.1,6670.7 5794.3,6665.2 5794.3,6659.7 ; 6407.6,4028 6408.4,4022.6 6409.9,4017.3 6412.2,4012.3 6415.1,4007.6 6418.6,4003.4 6422.7,3999.8 6427.2,3996.7 6432.2,3994.3 6437.4,3992.6 6442.8,3991.6 6448.3,3991.4 6453.8,3992 6459.1,3993.3 6464.2,3995.4 6468.9,3998.1 6473.3,4001.5 6477.1,4005.5 6480.3,4009.9 6482.9,4014.8 6484.8,4019.9 6485.9,4025.3 6486.3,4030.8 6485.9,4036.3 6484.8,4041.6 6482.9,4046.8 6480.3,4051.6 6477.1,4056.1 6473.3,4060 6468.9,4063.4 6464.2,4066.2 6459.1,4068.2 6453.8,4069.6 6448.3,4070.1 6442.8,4069.9 6437.4,4069 6432.2,4067.3 6427.2,4064.9 6422.7,4061.8 6418.6,4058.1 6415.1,4053.9 6412.2,4049.3 6409.9,4044.3 6408.4,4039 6407.6,4033.5 6407.6,4028 ; 6976.2,6391.8 6977,6386.3 6978.5,6381 6980.7,6376 6983.6,6371.4 6987.2,6367.1 6991.3,6363.5 6995.8,6360.4 7000.7,6358 7006,6356.3 7011.4,6355.3 7016.9,6355.2 7022.3,6355.7 7027.7,6357.1 7032.8,6359.1 7037.5,6361.9 7041.8,6365.2 7045.7,6369.2 7048.9,6373.6 7051.5,6378.5 7053.3,6383.6 7054.5,6389 7054.9,6394.5 7054.5,6400 7053.3,6405.3 7051.5,6410.5 7048.9,6415.4 7045.7,6419.8 7041.8,6423.8 7037.5,6427.1 7032.8,6429.9 7027.7,6431.9 7022.3,6433.3 7016.9,6433.8 7011.4,6433.7 7006,6432.7 7000.7,6431 6995.8,6428.6 6991.3,6425.5 6987.2,6421.8 6983.6,6417.6 6980.7,6413 6978.5,6408 6977,6402.7 6976.2,6397.2 6976.2,6391.8
  lines w10: 3116.9,4325.7 3116.9,6350.7 3190.2,6424 4256,6424 4302.6,6470.6 4302.6,6608.3 4442.5,6748.1 6989.2,6748.1 7102.5,6634.9 7102.5,4845.3 6952.6,4695.4 6588.4,4695.4 6560.7,4667.7 6560.7,3764 6385.3,3588.6 4315.4,3588.6 4250.4,3523.6 4250.4,3261.6 4190.5,3201.6 3795.2,3201.6 3559.9,3437 3213.5,3437 3162.4,3488.1 3162.4,4176.4 3118,4220.8 3118,4324.6 3116.9,4325.7

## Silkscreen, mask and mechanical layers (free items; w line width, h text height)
Top Silkscreen Layer:
  drawing of 701 lines, arcs and shapes, not listed
Bottom Silkscreen Layer:
  drawing of 695 lines, arcs and shapes, not listed
  text "SDA_ESP" at 6040,4920 h39.4
  text "SCL_ESP" at 5768.1,4855.5 h39.4
  text "GND" at 6852.9,4707.5 h45
  text "SCL_ESP" at 6080,4400 h39.4
  text "SDA_ESP" at 6100,4340 h39.4
  text "@TWNINKLY09" at 4845,3855 h120
Mechanical Layer:
  drawing of 315 lines, arcs and shapes, not listed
